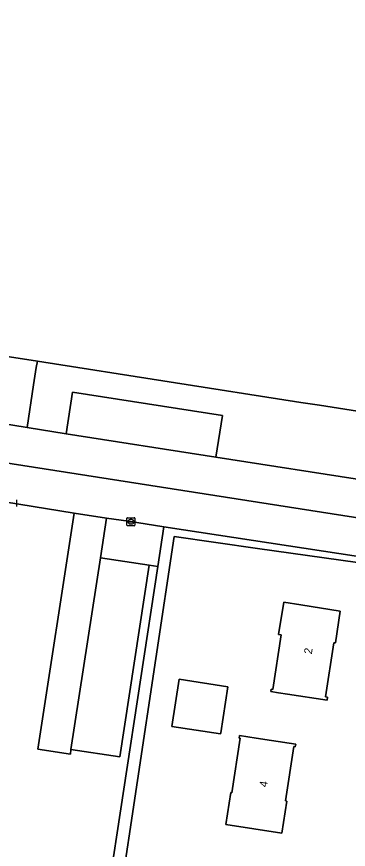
# Model space of a CAD drawing. Extents: x 161090 to 161692, y 379509 to 380907.
# Drawn here: x 161292.7 to 161334.2, y 380513 to 380617.1 of the extents above; entities that cross this region are included whole.
import ezdxf

# ---------------------------------------------------------------- set-up
doc = ezdxf.new("R2010")
doc.units = 0
for name, color, linetype in [('IMGEO_Erf', 7, 'Continuous'), ('IMGEO_Grasland_overig', 7, 'Continuous'), ('IMGEO_Groenvoorziening', 7, 'Continuous'), ('IMGEO_Hek', 7, 'Continuous'), ('IMGEO_Kolk', 7, 'Continuous'), ('IMGEO_Pand', 7, 'Continuous'), ('IMGEO_Pand_nummerreeks', 7, 'Continuous'), ('IMGEO_Parkeervlak_open', 7, 'Continuous'), ('IMGEO_Rijbaan_lokaal_gesloten', 7, 'Continuous'), ('IMGEO_Voetpad_open', 7, 'Continuous')]:
    doc.layers.add(name, color=color, linetype=linetype)

msp = doc.modelspace()

# ---------------------------------------------------------------- linework, layer by layer
at = {"layer": 'IMGEO_Erf'}
for points in [[(161337.49, 380524.35), (161337.6, 380525.04), (161338.46, 380530.68), (161339.31, 380536.22), (161339.44, 380537.08), (161341.12, 380548.06), (161339.48, 380548.29), (161338.75, 380548.39), (161335.35, 380548.88), (161322.85, 380550.65), (161312.4, 380552.13), (161305.54, 380506.41), (161304.91, 380502.17), (161302.9, 380488.82), (161328.43, 380484.89), (161329.75, 380484.69), (161329.57, 380483.71), (161330.4, 380483.57), (161332.95, 380483.13), (161336.97, 380509.33), (161335.22, 380509.64)], [(161324.49, 380532.76), (161324.54, 380533.04), (161324.74, 380533.01), (161325.8, 380539.83), (161325.49, 380539.88), (161326.12, 380543.92), (161328.26, 380543.59), (161333.2, 380542.82), (161332.58, 380538.83), (161332.41, 380538.85), (161331.36, 380532.11), (161331.61, 380532.08), (161331.55, 380531.67), (161326.61, 380532.43), (161325.49, 380532.61)], [(161318.25, 380527.62), (161318.23, 380527.48), (161312.14, 380528.41), (161313.05, 380534.3), (161319.13, 380533.37)], [(161326.33, 380519.09), (161326.5, 380519.06), (161325.89, 380515.08), (161318.9, 380516.16), (161319.51, 380520.14), (161319.62, 380520.12), (161320.68, 380526.93), (161320.54, 380526.95), (161320.59, 380527.26), (161322.68, 380526.94), (161324.6, 380526.64), (161327.62, 380526.17), (161327.57, 380525.87), (161327.39, 380525.9)]]:
    msp.add_lwpolyline(points, close=True, dxfattribs=at)
at = {"layer": 'IMGEO_Grasland_overig'}
msp.add_lwpolyline([(161290.16, 380566.39), (161294.03, 380565.76), (161294.81, 380571.09), (161295.17, 380573.26), (161295.3, 380574.05), (161290.75, 380574.76), (161288.53, 380575.11), (161288.16, 380572.76), (161262.04, 380576.82), (161255.07, 380531.35)], dxfattribs=at)
at = {"layer": 'IMGEO_Groenvoorziening'}
for points in [[(161310.38, 380548.37), (161309.29, 380548.54), (161305.63, 380524.59), (161299.51, 380525.52), (161299.45, 380524.93), (161295.37, 380525.55), (161299.89, 380555.06), (161286.02, 380557.3), (161281.23, 380525.9), (161267.1, 380528.09)], [(161257.94, 380520.89), (161252.31, 380519.35), (161247.98, 380518.77), (161261.6, 380513.37), (161304, 380506.66), (161310.38, 380548.37)]]:
    msp.add_lwpolyline(points, dxfattribs=at)
msp.add_lwpolyline([(161312.4, 380552.13), (161322.85, 380550.65), (161335.35, 380548.88), (161335.47, 380549.63), (161311.14, 380553.36), (161310.38, 380548.37), (161304, 380506.66), (161305.54, 380506.41)], close=True, dxfattribs=at)
at = {"layer": 'IMGEO_Hek'}
for points in [[(161322.85, 380550.65), (161312.4, 380552.13), (161305.54, 380506.41), (161304.91, 380502.17)], [(161335.35, 380548.88), (161322.85, 380550.65)]]:
    msp.add_lwpolyline(points, dxfattribs=at)
at = {"layer": 'IMGEO_Kolk'}
for p, q in [((161292.71, 380556.73), (161292.71, 380555.88)), ((161306.51, 380553.56), (161306.51, 380554.41)), ((161306.58, 380554.48), (161307.44, 380554.48)), ((161306.77, 380553.98), (161306.77, 380553.99)), ((161306.81, 380554.03), (161307.21, 380554.03)), ((161307.21, 380553.94), (161306.81, 380553.94)), ((161307.02, 380553.7), (161306.99, 380553.7)), ((161307, 380554.26), (161307.02, 380554.26)), ((161307.25, 380553.99), (161307.25, 380553.98)), ((161307.51, 380554.41), (161307.51, 380553.56)), ((161307.44, 380553.48), (161306.58, 380553.48))]:
    msp.add_line(p, q, dxfattribs=at)
for points in [[(161292.71, 380556.73), (161292.71, 380555.88)], [(161306.51, 380553.56), (161306.51, 380554.41)], [(161306.58, 380554.48), (161307.44, 380554.48)], [(161307.51, 380554.41), (161307.51, 380553.56)], [(161307.44, 380553.48), (161306.58, 380553.48)]]:
    msp.add_lwpolyline(points, dxfattribs=at)
for centre, radius, start, end in [((161306.59, 380554.41), 0.0765, 91.552, 178.448), ((161306.59, 380554.41), 0.0765, 91.552, 178.448), ((161306.81, 380553.99), 0.0403, 85.8775, 175.7526), ((161306.8, 380553.98), 0.0366, 178.938, 274.7102), ((161307.21, 380553.99), 0.0386, 1.7309, 96.639), ((161307.21, 380553.98), 0.043, 264.8664, 352.4533), ((161307.43, 380554.41), 0.0765, 1.552, 88.448), ((161307.43, 380554.41), 0.0765, 1.552, 88.448), ((161306.59, 380553.56), 0.0765, 181.552, 268.448), ((161306.59, 380553.56), 0.0765, 181.552, 268.448), ((161307.43, 380553.56), 0.0765, 271.552, 358.448), ((161307.43, 380553.56), 0.0765, 271.552, 358.448)]:
    msp.add_arc(centre, radius, start, end, dxfattribs=at)
for centre, major_axis, ratio, start_param, end_param in [((161307, 380553.98), (-0.387, 0.002), 0.722429, 4.712389, 7.853982), ((161307.02, 380553.98), (-0.39, 0.002), 0.717154, 1.570796, 4.712389)]:
    msp.add_ellipse(centre, major_axis=major_axis, ratio=ratio, start_param=start_param, end_param=end_param, dxfattribs=at)
at = {"layer": 'IMGEO_Pand'}
msp.add_lwpolyline([(161290.75, 380574.76), (161295.3, 380574.05), (161328.27, 380568.89), (161330.59, 380568.53), (161338.54, 380567.28), (161338.68, 380567.26), (161342.38, 380566.68), (161348.89, 380608.17), (161349.33, 380611), (161352.04, 380628.38)], dxfattribs=at)
for points in [[(161305.63, 380524.59), (161309.29, 380548.54), (161303.18, 380549.47), (161299.51, 380525.52)], [(161324.49, 380532.76), (161325.49, 380532.61), (161326.61, 380532.43), (161331.55, 380531.67), (161331.61, 380532.08), (161331.36, 380532.11), (161332.41, 380538.85), (161332.58, 380538.83), (161333.2, 380542.82), (161328.26, 380543.59), (161326.12, 380543.92), (161325.49, 380539.88), (161325.8, 380539.83), (161324.74, 380533.01), (161324.54, 380533.04)], [(161318.25, 380527.62), (161319.13, 380533.37), (161313.05, 380534.3), (161312.14, 380528.41), (161318.23, 380527.48)], [(161324.6, 380526.64), (161322.68, 380526.94), (161320.59, 380527.26), (161320.54, 380526.95), (161320.68, 380526.93), (161319.62, 380520.12), (161319.51, 380520.14), (161318.9, 380516.16), (161325.89, 380515.08), (161326.5, 380519.06), (161326.33, 380519.09), (161327.39, 380525.9), (161327.57, 380525.87), (161327.62, 380526.17)]]:
    msp.add_lwpolyline(points, close=True, dxfattribs=at)
at = {"layer": 'IMGEO_Parkeervlak_open'}
for points in [[(161318.46, 380567.26), (161299.69, 380570.17), (161298.89, 380564.96), (161317.65, 380562.05)], [(161286.78, 380562.06), (161286.02, 380557.3), (161299.89, 380555.06), (161303.95, 380554.44), (161306.71, 380554.04), (161311.14, 380553.36), (161335.47, 380549.63), (161335.62, 380550.61), (161336.04, 380553.34), (161336.2, 380554.34)]]:
    msp.add_lwpolyline(points, close=True, dxfattribs=at)
at = {"layer": 'IMGEO_Rijbaan_lokaal_gesloten'}
msp.add_lwpolyline([(161286.78, 380562.06), (161336.2, 380554.34), (161336.93, 380559.06), (161317.65, 380562.05), (161298.89, 380564.96), (161294.03, 380565.76), (161290.16, 380566.39)], dxfattribs=at)
at = {"layer": 'IMGEO_Voetpad_open'}
for points in [[(161338.5, 380566.2), (161338.68, 380567.26), (161338.54, 380567.28), (161330.59, 380568.53), (161328.27, 380568.89), (161295.3, 380574.05), (161295.17, 380573.26), (161294.81, 380571.09), (161294.03, 380565.76), (161298.89, 380564.96), (161299.69, 380570.17), (161318.46, 380567.26), (161317.65, 380562.05), (161336.93, 380559.06), (161337.21, 380559.02), (161337.34, 380559), (161337.64, 380560.87)], [(161303.18, 380549.47), (161303.95, 380554.44), (161299.89, 380555.06), (161295.37, 380525.55), (161299.45, 380524.93), (161299.51, 380525.52)], [(161311.14, 380553.36), (161306.71, 380554.04), (161303.95, 380554.44), (161303.18, 380549.47), (161309.29, 380548.54), (161310.38, 380548.37)]]:
    msp.add_lwpolyline(points, close=True, dxfattribs=at)

# ---------------------------------------------------------------- texts
at = {"layer": 'IMGEO_Pand_nummerreeks'}
for s, rotation, p in [('2', 81.1772, (161329.63, 380537.39)), ('4', 81.1781, (161324.04, 380520.77))]:
    msp.add_text(s, height=1, rotation=rotation, dxfattribs=at).set_placement(p)

doc.saveas('drawing.dxf')
